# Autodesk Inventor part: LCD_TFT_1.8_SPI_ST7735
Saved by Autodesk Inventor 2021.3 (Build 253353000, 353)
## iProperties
Created: 2023-07
Part Number: LCD_TFT_1.8_SPI_ST7735
Material: Generic
Document SubType Name: Modeling
Designer: AdminForWorker
Density: 1 g/cm^3
Appearance: Default
Title: LCD_TFT_1.8_SPI_ST7735 v1
Author: AdminForWorker
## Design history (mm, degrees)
feature "Body1"
feature "Body2"
feature "Body3"
feature "Body4"
feature "Body5"
feature "Body6"
feature "Body7"
feature "Body8"
feature "Body9"
feature "Body10"
feature "Body11"
feature "Body12"
feature "Body13"
feature "Body14"
feature "Body15"
feature "Body16"
feature "Body17"
feature "Body18"
feature "Body19"
feature "Body20"
feature "Body21"
feature "Body22"
feature "Body23"
feature "Body24"
feature "Body25"
feature "Body26"
feature "Body27"
feature "Body28"
feature "Body29"
feature "Body30"
feature "Body31"
body "Solid1"
body "Solid2"
body "Solid3"
body "Solid4"
body "Solid5"
body "Solid6"
body "Solid7"
body "Solid8"
body "Solid9"
body "Solid10"
body "Solid11"
body "Solid12"
body "Solid13"
body "Solid14"
body "Solid15"
body "Solid16"
body "Solid17"
body "Solid18"
body "Solid19"
body "Solid20"
body "Solid21"
body "Solid22"
body "Solid23"
body "Solid24"
body "Solid25"
body "Solid26"
body "Solid27"
body "Solid28"
body "Solid29"
body "Solid30"
body "Solid31"
